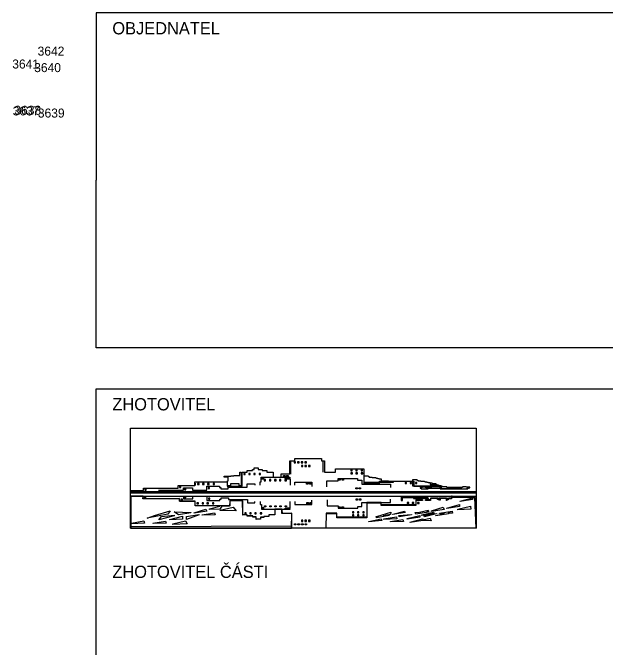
# Model space of a CAD drawing. Extents: x -740053 to -737517, y -1033516 to -1032488.
# Drawn here: x -738986.84 to -738950.62, y -1032616.05 to -1032577.23 of the extents above; entities that cross this region are included whole.
import ezdxf

# ---------------------------------------------------------------- set-up
doc = ezdxf.new("R2010")
doc.units = 0
doc.layers.add('bod-cislo', color=7, linetype='Continuous')
doc.layers.add('promika-rozp', color=7, linetype='Continuous')

# ---------------------------------------------------------------- blocks, each defined once
blk = doc.blocks.new('onegast')
for p, q in [((22.998, 7.759), (22.998, 9.646)), ((27.598, 8.019), (27.598, 9.571)), ((9.252, 6.105), (9.252, 6.463)), ((9.309, 6.102), (9.309, 6.46)), ((6.825, 5.723), (6.825, 6.082)), ((0.046, 5.264), (49.513, 5.263)), ((0.046, 5.075), (49.427, 5.075)), ((0.046, 4.561), (49.435, 4.561)), ((0.278, 5.186), (49.435, 5.186))]:
    blk.add_line(p, q)
for points in [[(0, 14.352), (49.53, 14.352), (49.53, 0), (0, 0)], [(23.451, 9.351), (23.667, 9.351), (23.667, 9.502), (23.451, 9.502)], [(23.957, 9.351), (24.173, 9.351), (24.173, 9.502), (23.957, 9.502)], [(24.48, 9.351), (24.696, 9.351), (24.696, 9.502), (24.48, 9.502)], [(24.994, 9.351), (25.21, 9.351), (25.21, 9.502), (24.994, 9.502)], [(24.501, 8.843), (24.717, 8.843), (24.717, 8.994), (24.501, 8.994)], [(25.007, 8.843), (25.223, 8.843), (25.223, 8.994), (25.007, 8.994)], [(25.53, 8.843), (25.746, 8.843), (25.746, 8.994), (25.53, 8.994)], [(21.914, 7.53), (22.13, 7.53), (22.13, 7.378), (21.914, 7.378)], [(22.377, 7.53), (22.593, 7.53), (22.593, 7.378), (22.377, 7.378)], [(19.161, 6.799), (19.377, 6.799), (19.377, 6.95), (19.161, 6.95)], [(25.216, 6.462), (25.432, 6.462), (25.432, 6.311), (25.216, 6.311)], [(25.679, 6.462), (25.895, 6.462), (25.895, 6.311), (25.679, 6.311)], [(29.857, 7.022), (30.073, 7.022), (30.073, 6.871), (29.857, 6.871)], [(30.32, 7.022), (30.536, 7.022), (30.536, 6.871), (30.32, 6.871)], [(32.298, 5.793), (32.514, 5.793), (32.514, 5.642), (32.298, 5.642)], [(32.761, 5.793), (32.977, 5.793), (32.977, 5.642), (32.761, 5.642)], [(25.286, 3.656), (25.502, 3.656), (25.502, 3.505), (25.286, 3.505)], [(25.749, 3.656), (25.965, 3.656), (25.965, 3.505), (25.749, 3.505)], [(32.333, 4.18), (32.549, 4.18), (32.549, 4.029), (32.333, 4.029)], [(32.796, 4.18), (33.012, 4.18), (33.012, 4.029), (32.796, 4.029)], [(12.874, 2.574), (14.701, 3.028), (15.132, 2.483), (12.879, 2.512)], [(19.195, 3.182), (19.411, 3.182), (19.411, 3.031), (19.195, 3.031)], [(29.843, 3.074), (30.059, 3.074), (30.059, 2.923), (29.843, 2.923)], [(30.306, 3.074), (30.522, 3.074), (30.522, 2.923), (30.306, 2.923)], [(3.464, 1.792), (5.689, 2.483), (5.353, 1.985), (2.388, 1.451)], [(4.449, 1.687), (6.263, 1.842), (6.277, 1.778), (4.06, 1.174)], [(6.257, 2.359), (8.663, 2.239), (8.678, 2.175), (6.892, 1.886)], [(8.049, 1.674), (9.825, 1.965), (9.84, 1.9), (8.039, 1.247)], [(9.139, 2.21), (10.813, 2.729), (10.929, 2.436), (9.143, 2.148)], [(10.285, 1.911), (12.061, 2.202), (12.15, 1.899), (10.289, 1.849)], [(0.161, 0.692), (1.912, 1.059), (2.012, 0.718), (0.165, 0.63)], [(3.24, 0.71), (5.016, 1), (5.119, 0.715), (3.244, 0.648)], [(5.644, 1.239), (7.471, 1.693), (7.457, 1.283), (5.649, 1.176)], [(6.077, 0.602), (7.903, 1.057), (8.126, 0.622), (6.081, 0.54)], [(24.501, 0.974), (24.717, 0.974), (24.717, 1.125), (24.501, 1.125)], [(25.007, 0.974), (25.223, 0.974), (25.223, 1.125), (25.007, 1.125)], [(25.53, 0.974), (25.746, 0.974), (25.746, 1.125), (25.53, 1.125)], [(23.485, 0.631), (23.701, 0.631), (23.701, 0.48), (23.485, 0.48)], [(23.99, 0.631), (24.206, 0.631), (24.206, 0.48), (23.99, 0.48)], [(24.513, 0.631), (24.729, 0.631), (24.729, 0.48), (24.513, 0.48)], [(25.028, 0.631), (25.244, 0.631), (25.244, 0.48), (25.028, 0.48)]]:
    blk.add_lwpolyline(points, close=True)
for points in [[(0.046, 5.405), (1.862, 5.405), (1.862, 5.731), (6.84, 5.731), (6.84, 6.109), (9.238, 6.109), (9.238, 6.643), (13.878, 6.643), (13.878, 6.005), (16.015, 6.005), (16.015, 8.023), (16.706, 8.023), (16.706, 8.284), (17.475, 8.284), (17.475, 8.401), (17.749, 8.401), (17.749, 8.662), (18.296, 8.662), (18.296, 8.388), (18.879, 8.388), (18.879, 8.272), (19.556, 8.272), (19.556, 8.037), (20.443, 8.037), (20.443, 7.282), (21.616, 7.282), (21.616, 7.764), (22.841, 7.764), (22.841, 9.665), (23.57, 9.665), (23.57, 9.994), (27.389, 9.994), (27.389, 9.629), (27.806, 9.629), (27.806, 8.014), (29.37, 8.014), (29.37, 8.522), (33.462, 8.522), (33.462, 6.412), (35.707, 6.412), (35.707, 6.737), (40.62, 6.737), (40.62, 6.034), (44.351, 6.034), (44.351, 5.656), (48.313, 5.656)], [(31.563, 8.207), (31.779, 8.207), (31.779, 8.358), (31.563, 8.358), (31.563, 8.207)], [(32.276, 8.207), (32.493, 8.207), (32.493, 8.358), (32.276, 8.358), (32.276, 8.207)], [(33.049, 8.207), (33.265, 8.207), (33.265, 8.358), (33.049, 8.358), (33.049, 8.207)], [(14.328, 6.074), (13.905, 6.074), (13.905, 6.765), (14, 6.765), (14, 7.326), (13.453, 7.326), (13.453, 7.425), (14.378, 7.425), (14.378, 7.475), (14.825, 7.475), (14.825, 7.544), (15.233, 7.544), (15.273, 7.544), (15.68, 7.544), (15.68, 8.021), (15.879, 8.021), (15.879, 6.074), (15.571, 6.074), (15.571, 6.362), (14.328, 6.362), (14.328, 6.074)], [(16.228, 7.685), (16.444, 7.685), (16.444, 7.836), (16.228, 7.836), (16.228, 7.685)], [(16.952, 7.685), (17.168, 7.685), (17.168, 7.836), (16.952, 7.836), (16.952, 7.685)], [(17.666, 7.685), (17.882, 7.685), (17.882, 7.836), (17.666, 7.836), (17.666, 7.685)], [(18.439, 7.685), (18.655, 7.685), (18.655, 7.836), (18.439, 7.836), (18.439, 7.685)], [(18.576, 6.169), (18.576, 6.617), (18.746, 6.617), (18.746, 7.081), (19.149, 7.081), (19.149, 7.081), (18.746, 7.081), (18.746, 7.282), (22.862, 7.282), (22.862, 7.282), (22.862, 7.183), (22.396, 7.183), (22.396, 7.088), (22.871, 7.088), (22.871, 6.157)], [(22.141, 7.131), (22.357, 7.131), (22.357, 7.282), (22.141, 7.282), (22.141, 7.131)], [(31.581, 7.761), (31.797, 7.761), (31.797, 7.913), (31.581, 7.913), (31.581, 7.761)], [(32.295, 7.761), (32.511, 7.761), (32.511, 7.913), (32.295, 7.913), (32.295, 7.761)], [(33.067, 7.761), (33.284, 7.761), (33.284, 7.913), (33.067, 7.913), (33.067, 7.761)], [(37.637, 6.532), (33.482, 6.532), (33.482, 7.473), (34.037, 7.473), (34.037, 7.386), (34.193, 7.386), (34.193, 7.317), (34.616, 7.317), (34.616, 7.275), (35.159, 7.275), (35.159, 7.197), (35.257, 7.197), (35.257, 7.144), (35.467, 7.144), (35.467, 7.095), (35.652, 7.095), (35.652, 7.062), (35.94, 7.062), (35.94, 6.779), (36.976, 6.779), (36.976, 6.725), (37.165, 6.725), (37.165, 6.639), (37.502, 6.639), (37.502, 6.565), (37.637, 6.565), (37.637, 6.532)], [(9.628, 6.243), (9.844, 6.243), (9.844, 6.394), (9.628, 6.394), (9.628, 6.243)], [(10.353, 6.243), (10.569, 6.243), (10.569, 6.394), (10.353, 6.394), (10.353, 6.243)], [(11.067, 6.243), (11.283, 6.243), (11.283, 6.394), (11.067, 6.394), (11.067, 6.243)], [(11.839, 6.243), (12.055, 6.243), (12.055, 6.394), (11.839, 6.394), (11.839, 6.243)], [(19.919, 6.799), (20.135, 6.799), (20.135, 6.95), (19.919, 6.95), (19.919, 6.799)], [(20.644, 6.799), (20.86, 6.799), (20.86, 6.95), (20.644, 6.95), (20.644, 6.799)], [(21.358, 6.799), (21.574, 6.799), (21.574, 6.95), (21.358, 6.95), (21.358, 6.799)], [(22.13, 6.799), (22.346, 6.799), (22.346, 6.95), (22.13, 6.95), (22.13, 6.799)], [(23.534, 6.16), (23.534, 6.579), (25.98, 6.579), (25.98, 5.951)], [(28.148, 5.929), (28.148, 6.792), (28.724, 6.792), (28.724, 6.792), (29.741, 6.792), (29.741, 7.118), (30.144, 7.118), (30.144, 7.118), (30.97, 7.118), (30.97, 7.118), (32.543, 7.118), (32.543, 6.888), (33.138, 6.888), (33.138, 6.313), (37.246, 6.313), (37.246, 5.833)], [(39.341, 6.398), (39.557, 6.398), (39.557, 6.549), (39.341, 6.549), (39.341, 6.398)], [(40.055, 6.398), (40.271, 6.398), (40.271, 6.549), (40.055, 6.549), (40.055, 6.398)], [(40.466, 6.007), (40.466, 6.948), (41.021, 6.948), (41.021, 6.861), (41.177, 6.861), (41.177, 6.792), (41.6, 6.792), (41.6, 6.75), (42.143, 6.75), (42.143, 6.672), (42.241, 6.672), (42.241, 6.619), (42.451, 6.619), (42.451, 6.57), (42.636, 6.57), (42.636, 6.537), (42.924, 6.537), (42.924, 6.254), (43.96, 6.254), (43.96, 6.2), (44.149, 6.2), (44.149, 6.114), (44.486, 6.114), (44.486, 6.04), (44.622, 6.04), (44.622, 6.007), (40.466, 6.007)], [(44.622, 6.007), (40.466, 6.007), (40.466, 6.948), (41.021, 6.948), (41.021, 6.861), (41.177, 6.861), (41.177, 6.792), (41.6, 6.792), (41.6, 6.75), (42.143, 6.75), (42.143, 6.672), (42.241, 6.672), (42.241, 6.619), (42.451, 6.619), (42.451, 6.57), (42.636, 6.57), (42.636, 6.537), (42.924, 6.537), (42.924, 6.254), (43.96, 6.254), (43.96, 6.2), (44.149, 6.2), (44.149, 6.114), (44.486, 6.114), (44.486, 6.04), (44.622, 6.04), (44.622, 6.007)], [(40.827, 6.398), (41.043, 6.398), (41.043, 6.549), (40.827, 6.549), (40.827, 6.398)], [(42.958, 6.466), (42.958, 6.276), (43.791, 6.276), (43.791, 6.348), (43.516, 6.348), (43.516, 6.365), (43.342, 6.365), (43.342, 6.413), (43.192, 6.413), (43.192, 6.466), (42.958, 6.466)], [(43.192, 6.466), (42.958, 6.466), (42.958, 6.276), (43.791, 6.276), (43.791, 6.348), (43.516, 6.348), (43.516, 6.365), (43.342, 6.365), (43.342, 6.413), (43.192, 6.413), (43.192, 6.466)], [(2.06, 5.439), (2.276, 5.439), (2.276, 5.591), (2.06, 5.591), (2.06, 5.439)], [(4.051, 5.42), (7.596, 5.42), (7.596, 5.765), (8.897, 5.765), (8.897, 5.42), (10.933, 5.42), (10.933, 6.01), (12.761, 6.01), (12.761, 5.826), (12.957, 5.826), (12.957, 5.643), (14, 5.643), (14, 5.888), (16.736, 5.888), (16.736, 6.366), (17.815, 6.366), (17.815, 6.145)], [(7.024, 5.813), (7.24, 5.813), (7.24, 5.964), (7.024, 5.964), (7.024, 5.813)], [(7.749, 5.505), (7.965, 5.505), (7.965, 5.656), (7.749, 5.656), (7.749, 5.505)], [(11.131, 5.681), (11.348, 5.681), (11.348, 5.832), (11.131, 5.832), (11.131, 5.681)], [(41.512, 5.831), (41.512, 5.707), (41.669, 5.707), (41.669, 5.636), (42.598, 5.636), (42.598, 5.694), (42.709, 5.694), (42.709, 5.727), (44.282, 5.727), (44.282, 5.811), (44.431, 5.811), (44.431, 5.844), (44.516, 5.844), (44.516, 5.681), (45.309, 5.681), (45.309, 5.74), (45.433, 5.74), (45.433, 5.779), (45.491, 5.779), (45.491, 5.805), (47.253, 5.805), (47.253, 5.707), (47.396, 5.707), (47.396, 5.649), (48.254, 5.649), (48.254, 5.727), (48.443, 5.727), (48.443, 5.785), (48.599, 5.785), (48.599, 5.87), (48.098, 5.87), (48.098, 5.922), (47.578, 5.922), (47.578, 5.831), (45.335, 5.831), (45.335, 5.902), (44.425, 5.902), (44.425, 5.772), (44.282, 5.772), (44.282, 5.746), (42.702, 5.746), (42.702, 5.811), (42.826, 5.811), (42.826, 5.967), (43.196, 5.967), (43.196, 6.019), (42.546, 6.019), (42.546, 5.863), (42.683, 5.863), (42.683, 5.798), (42.332, 5.798), (42.332, 5.87), (41.838, 5.87), (41.838, 5.824), (41.512, 5.831)], [(44.282, 5.727), (44.282, 5.746), (42.702, 5.746), (42.702, 5.811), (42.826, 5.811), (42.826, 5.967), (43.196, 5.967), (43.196, 6.019), (42.546, 6.019), (42.546, 5.863), (42.683, 5.863), (42.683, 5.798), (42.332, 5.798), (42.332, 5.87), (41.838, 5.87), (41.838, 5.824), (41.512, 5.831), (41.512, 5.707), (41.669, 5.707), (41.669, 5.636), (42.598, 5.636), (42.598, 5.694), (42.709, 5.694), (42.709, 5.727), (44.282, 5.727)], [(44.425, 5.772), (44.425, 5.811), (44.282, 5.811), (44.282, 5.772), (44.425, 5.772)], [(44.425, 5.902), (44.425, 5.811), (44.431, 5.811), (44.431, 5.844), (44.516, 5.844), (44.516, 5.681), (45.309, 5.681), (45.309, 5.74), (45.433, 5.74), (45.433, 5.779), (45.491, 5.779), (45.491, 5.805), (47.253, 5.805), (47.253, 5.707), (47.396, 5.707), (47.396, 5.649), (48.254, 5.649), (48.254, 5.727), (48.443, 5.727), (48.443, 5.785), (48.599, 5.785), (48.599, 5.87), (48.098, 5.87), (48.098, 5.922), (47.578, 5.922), (47.578, 5.831), (45.335, 5.831), (45.335, 5.902), (44.425, 5.902)], [(0.036, 4.579), (0.065, 0.028), (23.119, 0.038), (23.133, 2.114), (21.714, 2.114), (21.714, 2.699), (20.694, 2.699), (20.694, 1.928), (19.819, 1.928), (19.819, 1.69), (19.103, 1.69), (19.103, 1.544), (18.625, 1.544), (18.625, 1.266), (18.029, 1.266), (18.029, 1.57), (17.525, 1.57), (17.525, 1.716), (16.716, 1.716), (16.716, 1.902), (16.093, 1.902), (16.093, 3.915), (14.237, 3.915), (14.237, 3.187), (9.292, 3.187), (9.292, 3.849), (7.039, 3.849), (7.039, 4.233), (1.802, 4.196), (1.811, 4.57), (0.036, 4.579)], [(4.084, 4.561), (7.63, 4.561), (7.63, 4.216), (8.93, 4.216), (8.93, 4.561), (10.967, 4.561), (10.967, 3.971), (12.794, 3.971), (12.794, 4.155), (12.991, 4.155), (12.991, 4.339), (14.034, 4.339), (14.034, 4.094), (16.769, 4.094), (16.769, 3.616), (17.849, 3.616), (17.849, 3.836)], [(28.067, 2.141), (27.991, 0.053), (49.525, -0.002), (49.509, 4.521), (46.076, 4.473), (46.076, 4.57), (46.005, 4.57), (46.005, 4.306), (45.632, 4.306), (45.632, 4.229), (45.529, 4.229), (45.529, 4.146), (45.439, 4.146), (45.349, 4.146), (45.349, 4.036), (45.259, 4.036), (45.259, 4.191), (45.439, 4.146), (45.439, 4.22), (45.439, 4.224), (45.471, 4.224), (45.471, 4.269), (45.282, 4.269), (45.282, 4.316), (44.334, 4.316), (44.334, 4.273), (44.184, 4.273), (44.184, 4.213), (44.287, 4.213), (44.287, 4.176), (44.394, 4.176), (44.394, 4.118), (44.258, 4.118), (44.258, 4.164), (44.068, 4.164), (44.068, 4.218), (44.012, 4.218), (44.012, 4.265), (44.086, 4.265), (44.086, 4.318), (42.971, 4.318), (42.971, 4.076), (42.289, 4.076), (42.289, 4.126), (42.5, 4.126), (42.5, 4.175), (42.652, 4.175), (42.652, 4.222), (42.701, 4.222), (42.701, 4.269), (42.514, 4.269), (42.514, 4.327), (42.596, 4.327), (42.596, 4.458), (42.482, 4.458), (42.482, 4.525), (42.389, 4.525), (42.389, 4.36), (40.819, 4.36), (40.819, 4.547), (40.717, 4.547), (40.717, 4.494), (40.569, 4.494), (40.569, 4.52), (38.993, 4.52), (38.993, 4.465), (40.564, 4.465), (40.564, 4.316), (41.633, 4.316), (41.633, 4.278), (41.484, 4.278), (41.484, 4.169), (41.635, 4.169), (41.635, 4.12), (41.831, 4.12), (41.831, 4.071), (40.874, 4.071), (40.874, 3.353), (35.926, 3.353), (35.926, 3.66), (33.862, 3.66), (33.862, 1.575), (29.594, 1.575), (29.594, 2.142), (28.067, 2.141)], [(0.02, 0.014), (23.093, 0.002), (23.125, 2.114), (22.3, 2.114), (21.766, 2.106), (21.766, 2.114), (21.714, 2.114), (21.714, 2.69), (20.694, 2.699), (20.694, 2.513), (20.708, 1.897), (19.841, 1.924), (19.841, 1.714), (19.819, 1.714), (19.819, 1.69), (19.163, 1.69), (19.103, 1.687), (19.103, 1.544), (18.635, 1.544), (18.625, 1.386), (18.625, 1.266), (18.256, 1.266), (18.026, 1.258), (18.017, 1.57), (17.525, 1.57), (17.525, 1.716), (16.716, 1.716), (16.716, 1.896), (16.101, 1.86), (16.101, 1.902), (16.093, 1.902), (16.093, 2.719), (16.083, 3.915), (14.514, 3.915), (14.249, 3.911), (14.237, 3.714), (14.237, 3.187), (14.206, 3.187), (14.203, 3.146), (13.089, 3.156), (12.812, 2.735), (11.338, 2.693), (11.334, 2.755), (12.803, 3.159), (9.776, 3.187), (9.292, 3.187), (9.292, 3.191), (9.287, 3.191), (9.292, 3.593), (9.292, 3.82), (7.066, 3.831), (7.065, 3.849), (7.039, 3.849), (7.039, 4.196), (2.893, 4.204), (2.028, 4.198), (1.802, 4.187), (1.803, 4.196), (1.802, 4.196), (1.81, 4.518), (0.042, 4.506), (0.02, 0.014)], [(0.042, 4.506), (0.03, 0.238), (23.125, 0.347), (23.125, 2.125), (21.766, 2.106), (21.748, 2.69), (20.689, 2.699), (20.708, 1.897), (19.841, 1.924), (19.841, 1.714), (19.093, 1.687), (19.093, 1.559), (18.637, 1.568), (18.619, 1.277), (18.026, 1.258), (18.017, 1.605), (17.542, 1.596), (17.542, 1.769), (16.721, 1.751), (16.73, 1.897), (16.101, 1.86), (16.083, 3.939), (14.249, 3.911), (14.203, 3.146), (9.287, 3.191), (9.296, 3.82), (7.066, 3.831), (7.048, 4.196), (2.185, 4.205), (1.802, 4.187), (1.821, 4.518), (0.042, 4.506)], [(1.994, 4.298), (2.21, 4.298), (2.21, 4.449), (1.994, 4.449), (1.994, 4.298)], [(7.243, 3.99), (7.46, 3.99), (7.46, 4.142), (7.243, 4.142), (7.243, 3.99)], [(7.727, 4.32), (7.943, 4.32), (7.943, 4.471), (7.727, 4.471), (7.727, 4.32)], [(11.175, 4.166), (11.391, 4.166), (11.391, 4.317), (11.175, 4.317), (11.175, 4.166)], [(18.61, 3.813), (18.61, 3.364), (18.78, 3.364), (18.78, 2.9), (19.182, 2.9), (19.182, 2.9), (18.78, 2.9), (18.78, 2.699), (22.895, 2.699), (22.895, 2.699), (22.895, 2.799), (22.429, 2.799), (22.429, 2.894), (22.904, 2.894), (22.904, 3.824)], [(23.568, 3.821), (23.568, 3.403), (26.014, 3.403), (26.014, 4.03)], [(28.067, 2.05), (27.99, 0.054), (49.512, 0.016), (49.361, 4.382), (46.076, 4.382), (46.076, 4.478), (46.005, 4.478), (46.005, 4.215), (45.632, 4.215), (45.632, 4.138), (45.529, 4.138), (45.529, 4.054), (45.349, 4.054), (45.349, 3.945), (45.259, 3.945), (45.259, 4.099), (45.439, 4.054), (45.439, 4.129), (45.439, 4.133), (45.471, 4.133), (45.471, 4.178), (45.282, 4.178), (45.282, 4.224), (44.334, 4.224), (44.334, 4.182), (44.184, 4.182), (44.184, 4.122), (44.287, 4.122), (44.287, 4.084), (44.394, 4.084), (44.394, 4.026), (44.258, 4.026), (44.258, 4.073), (44.068, 4.073), (44.068, 4.127), (44.012, 4.127), (44.012, 4.173), (44.086, 4.173), (44.086, 4.227), (42.971, 4.227), (42.971, 3.984), (42.289, 3.984), (42.289, 4.035), (42.5, 4.035), (42.5, 4.084), (42.652, 4.084), (42.652, 4.131), (42.701, 4.131), (42.701, 4.178), (42.514, 4.178), (42.514, 4.235), (42.596, 4.235), (42.596, 4.367), (42.482, 4.367), (42.482, 4.433), (42.389, 4.433), (42.389, 4.269), (40.819, 4.269), (40.819, 4.456), (40.717, 4.456), (40.717, 4.402), (40.569, 4.402), (40.569, 4.429), (38.993, 4.429), (38.993, 4.376), (38.881, 4.376), (38.881, 4.427), (38.792, 4.427), (38.792, 3.942), (38.993, 3.942), (38.993, 4.374), (40.564, 4.374), (40.564, 4.225), (41.633, 4.225), (41.633, 4.187), (41.484, 4.187), (41.484, 4.078), (41.635, 4.078), (41.635, 4.029), (41.831, 4.029), (41.831, 3.98), (40.874, 3.98), (40.874, 3.262), (35.926, 3.262), (35.926, 3.569), (33.862, 3.569), (33.862, 1.483), (29.594, 1.483), (29.594, 2.051), (28.067, 2.05)], [(28.182, 4.052), (28.182, 3.189), (28.757, 3.189), (28.757, 3.189), (29.775, 3.189), (29.775, 2.863), (30.178, 2.863), (30.178, 2.863), (31.003, 2.863), (31.003, 2.863), (32.577, 2.863), (32.577, 3.093), (33.172, 3.093), (33.172, 3.669), (37.279, 3.669), (37.279, 4.148)], [(39.65, 3.525), (39.866, 3.525), (39.866, 3.677), (39.65, 3.677), (39.65, 3.525)], [(40.364, 3.525), (40.58, 3.525), (40.58, 3.677), (40.364, 3.677), (40.364, 3.525)], [(41.136, 3.525), (41.352, 3.525), (41.352, 3.677), (41.136, 3.677), (41.136, 3.525)], [(49.007, 4.105), (47.221, 3.817), (47.216, 3.879), (49.043, 4.334), (49.007, 4.105)], [(9.536, 3.464), (9.752, 3.464), (9.752, 3.615), (9.536, 3.615), (9.536, 3.464)], [(10.26, 3.464), (10.476, 3.464), (10.476, 3.615), (10.26, 3.615), (10.26, 3.464)], [(10.974, 3.464), (11.19, 3.464), (11.19, 3.615), (10.974, 3.615), (10.974, 3.464)], [(11.746, 3.464), (11.963, 3.464), (11.963, 3.615), (11.746, 3.615), (11.746, 3.464)], [(15.132, 2.483), (12.879, 2.512), (12.874, 2.574), (14.701, 3.028), (15.132, 2.483)], [(19.195, 3.031), (19.195, 3.182), (19.411, 3.182), (19.411, 3.031), (19.195, 3.031)], [(20.169, 3.031), (19.953, 3.031), (19.953, 3.182), (20.169, 3.182), (20.169, 3.031)], [(20.893, 3.031), (20.677, 3.031), (20.677, 3.182), (20.893, 3.182), (20.893, 3.031)], [(21.607, 3.031), (21.391, 3.031), (21.391, 3.182), (21.607, 3.182), (21.607, 3.031)], [(22.38, 3.031), (22.164, 3.031), (22.164, 3.182), (22.38, 3.182), (22.38, 3.031)], [(22.39, 2.699), (22.174, 2.699), (22.174, 2.85), (22.39, 2.85), (22.39, 2.699)], [(44.937, 2.689), (43.151, 2.401), (43.147, 2.463), (44.821, 2.982), (44.937, 2.689)], [(47.132, 3.109), (45.346, 2.82), (45.342, 2.882), (47.162, 3.382), (47.132, 3.109)], [(48.753, 2.715), (46.887, 2.639), (46.882, 2.701), (48.709, 3.155), (48.753, 2.715)], [(2.388, 1.451), (3.464, 1.792), (5.689, 2.483), (5.353, 1.985), (2.388, 1.451)], [(4.06, 1.174), (4.449, 1.687), (6.263, 1.842), (6.277, 1.778), (4.06, 1.174)], [(6.892, 1.886), (6.257, 2.359), (8.663, 2.239), (8.678, 2.175), (6.892, 1.886)], [(8.039, 1.247), (8.049, 1.674), (9.825, 1.965), (9.84, 1.9), (8.039, 1.247)], [(9.143, 2.148), (9.139, 2.21), (10.813, 2.729), (10.929, 2.436), (9.143, 2.148)], [(10.289, 1.849), (10.285, 1.911), (12.061, 2.202), (12.15, 1.899), (10.289, 1.849)], [(16.383, 2.065), (16.599, 2.065), (16.599, 2.216), (16.383, 2.216), (16.383, 2.065)], [(17.107, 2.065), (17.324, 2.065), (17.324, 2.216), (17.107, 2.216), (17.107, 2.065)], [(17.821, 2.065), (18.037, 2.065), (18.037, 2.216), (17.821, 2.216), (17.821, 2.065)], [(18.594, 2.065), (18.81, 2.065), (18.81, 2.216), (18.594, 2.216), (18.594, 2.065)], [(31.804, 2.197), (32.02, 2.197), (32.02, 2.348), (31.804, 2.348), (31.804, 2.197)], [(31.804, 1.752), (32.02, 1.752), (32.02, 1.903), (31.804, 1.903), (31.804, 1.752)], [(32.518, 2.197), (32.734, 2.197), (32.734, 2.348), (32.518, 2.348), (32.518, 2.197)], [(32.518, 1.752), (32.734, 1.752), (32.734, 1.903), (32.518, 1.903), (32.518, 1.752)], [(33.29, 2.197), (33.506, 2.197), (33.506, 2.348), (33.29, 2.348), (33.29, 2.197)], [(33.29, 1.752), (33.506, 1.752), (33.506, 1.903), (33.29, 1.903), (33.29, 1.752)], [(37.045, 1.826), (35.275, 1.483), (35.212, 1.656), (35.458, 1.687), (35.456, 1.725), (37.304, 2.273), (37.246, 1.951), (36.232, 1.787), (37.03, 1.89), (37.045, 1.826)], [(39.361, 2.237), (37.575, 1.949), (37.57, 2.011), (39.263, 2.411), (39.361, 2.237)], [(40.285, 1.905), (38.499, 1.617), (38.457, 1.814), (40.271, 1.97), (40.285, 1.905)], [(41.443, 1.592), (39.657, 1.304), (39.653, 1.366), (41.479, 1.82), (41.443, 1.592)], [(42.686, 2.302), (40.9, 2.014), (40.791, 2.246), (41.431, 2.287), (42.647, 2.574), (42.745, 2.401), (42.436, 2.351), (42.671, 2.366), (42.686, 2.302)], [(43.522, 2.115), (41.736, 1.826), (41.732, 1.888), (43.425, 2.288), (43.522, 2.115)], [(43.848, 2.028), (42.108, 1.637), (42.057, 1.801), (43.833, 2.092), (43.848, 2.028)], [(45.555, 2.06), (43.769, 1.772), (43.765, 1.834), (44.98, 2.121), (44.297, 2.102), (44.293, 2.164), (46.069, 2.455), (46.158, 2.152), (45.513, 2.135), (45.555, 2.06)], [(0.165, 0.63), (0.161, 0.692), (1.912, 1.059), (2.012, 0.718), (0.165, 0.63)], [(3.244, 0.648), (3.24, 0.71), (5.016, 1), (5.119, 0.715), (3.244, 0.648)], [(5.649, 1.176), (5.644, 1.239), (7.471, 1.693), (7.457, 1.283), (5.649, 1.176)], [(6.081, 0.54), (6.077, 0.602), (7.903, 1.057), (8.126, 0.622), (6.081, 0.54)], [(35.996, 1.11), (34.173, 0.883), (34.169, 0.945), (35.92, 1.312), (35.996, 1.11)], [(38.172, 1.324), (36.328, 1.254), (36.324, 1.316), (38.1, 1.607), (38.172, 1.324)], [(39.127, 0.968), (37.252, 0.901), (37.248, 0.963), (39.024, 1.253), (39.127, 0.968)], [(41.875, 1.082), (40.089, 0.793), (40.085, 0.855), (41.911, 1.31), (41.894, 1.2), (42.92, 1.442), (43.064, 1.042), (41.875, 1.085), (41.875, 1.082)]]:
    blk.add_lwpolyline(points)

msp = doc.modelspace()

# ---------------------------------------------------------------- linework, layer by layer
at = {"layer": 'promika-rozp'}
for points in [[(-738891.749, -1032587.478), (-738891.749, -1032577.228), (-738981.749, -1032577.228), (-738981.749, -1032587.478)], [(-738891.749, -1032587.478), (-738891.749, -1032597.728), (-738981.749, -1032597.728), (-738981.749, -1032587.478)], [(-738981.749, -1032620.728), (-738981.749, -1032600.228), (-738891.749, -1032600.228), (-738891.749, -1032620.728)]]:
    msp.add_lwpolyline(points, dxfattribs=at)

# ---------------------------------------------------------------- block references
at = {"xscale": 0.4267458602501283, "yscale": 0.4267458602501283, "rotation": -2.645829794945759e-12}
msp.add_blockref('onegast', (-738979.648, -1032608.757), dxfattribs=at)

# ---------------------------------------------------------------- texts
at = {"layer": 'bod-cislo'}
for s, p in [('3642', (-738985.318, -1032579.853)), ('3641', (-738986.869, -1032580.643)), ('3640', (-738985.528, -1032580.863)), ('3637', (-738986.838, -1032583.513)), ('3638', (-738986.738, -1032583.473)), ('3639', (-738985.305, -1032583.643))]:
    msp.add_text(s, height=0.55, dxfattribs=at).set_placement(p)
at = {"layer": 'promika-rozp'}
for s, p in [('OBJEDNATEL', (-738980.751, -1032578.554)), ('ZHOTOVITEL', (-738980.751, -1032601.554)), ('ZHOTOVITEL ČÁSTI', (-738980.751, -1032611.804))]:
    msp.add_text(s, height=0.75, rotation=360, dxfattribs=at).set_placement(p)

doc.saveas('drawing.dxf')
